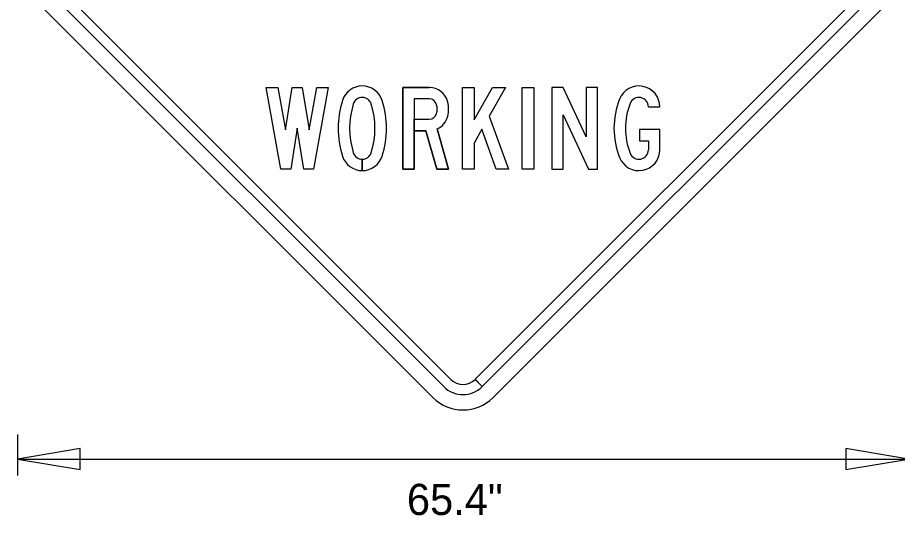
# Model space of a CAD drawing. Extents: x 0 to 770, y 0 to 495.
# Drawn here: x 425.3 to 524.2, y 356.5 to 412.5 of the extents above; entities that cross this region are included whole.
import ezdxf

# ---------------------------------------------------------------- set-up
doc = ezdxf.new("R2010")
doc.units = 0
for name, color, linetype in [('Dimension', 7, 'Continuous'), ('GSBWFill', 7, 'Continuous'), ('GSColorFill', 7, 'Continuous'), ('GSDims', 7, 'Continuous'), ('GSOutline', 7, 'Continuous'), ('TextStructures', 7, 'Continuous')]:
    doc.layers.add(name, color=color, linetype=linetype)

msp = doc.modelspace()

# ---------------------------------------------------------------- linework, layer by layer
at = {"layer": 'Dimension'}
for points in [[(425.301, 362.828), (432.318, 361.639), (432.318, 364.017)], [(525.425, 362.828), (518.409, 364.017), (518.409, 361.639)]]:
    msp.add_lwpolyline(points, close=True, dxfattribs=at)
at = {"layer": 'GSBWFill'}
for p, q in [((474.008, 371.785), (428.738, 417.055)), ((521.989, 417.055), (476.727, 371.793)), ((427.924, 416.242), (473.195, 370.972)), ((477.54, 370.98), (522.802, 416.242)), ((426.705, 415.022), (471.975, 369.752)), ((478.752, 369.752), (524.022, 415.022)), ((496.203, 402.424), (497.491, 402.424)), ((471.557, 401.021), (471.557, 401.021)), ((496.203, 398.583), (496.203, 397.594)), ((464.046, 395.248), (464.046, 396.536)), ((464.047, 396.536), (464.047, 395.248)), ((477.532, 370.972), (476.719, 371.785)), ((476.727, 371.793), (477.54, 370.98))]:
    msp.add_line(p, q, dxfattribs=at)
for points in [[(455.401, 399.848), (456.163, 404.609), (457.3, 404.609), (458.062, 399.848), (458.919, 404.609), (460.228, 404.609), (458.572, 395.409), (457.468, 395.409), (456.732, 400.009), (455.996, 395.409), (454.892, 395.409), (453.235, 404.609), (454.544, 404.609)], [(477.487, 399.91), (476.605, 398.353), (476.605, 395.409), (475.317, 395.409), (475.317, 404.609), (476.605, 404.609), (476.605, 400.967), (478.667, 404.609), (480.148, 404.609), (478.324, 401.389), (480.47, 395.409), (479.101, 395.409)], [(482.034, 404.609), (483.322, 404.609), (483.322, 395.409), (482.034, 395.409)], [(489.486, 395.409), (490.498, 395.409), (490.498, 404.609), (489.21, 404.609), (489.21, 399.05), (486.618, 404.609), (485.346, 404.609), (485.346, 395.409), (486.634, 395.409), (486.634, 401.527)]]:
    msp.add_lwpolyline(points, close=True, dxfattribs=at)
for points in [[(471.557, 403.321), (469.889, 403.321), (469.889, 395.409), (468.601, 395.409), (468.601, 404.609), (471.557, 404.609)], [(472.465, 399.933), (473.753, 395.409), (472.414, 395.409), (471.183, 399.733), (469.889, 399.733), (469.889, 401.021), (471.557, 401.021)], [(497.491, 397.594), (497.491, 399.871), (495.191, 399.871), (495.191, 398.583), (496.203, 398.583)]]:
    msp.add_lwpolyline(points, dxfattribs=at)
for centre, radius, start, end in [((464.046, 402.424), 2.346, 17.32827, 162.67173), ((471.557, 402.447), 2.162, 13.88654, 90), ((495.145, 402.424), 2.346, 0, 158.43141), ((471.787, 400.009), 10.455, 162.67173, 197.32827), ((471.787, 400.009), 9.167, 162.67173, 197.32827), ((464.046, 402.424), 1.058, 17.32827, 162.67173), ((456.305, 400.009), 9.167, 342.67173, 17.32827), ((456.305, 400.009), 10.455, 342.67173, 17.32827), ((471.557, 402.447), 0.874, 13.88654, 90), ((470.441, 402.171), 2.024, 346.11346, 13.88654), ((470.441, 402.171), 3.312, 346.11346, 13.88654), ((501.255, 400.009), 8.916, 158.43141, 201.5686), ((501.255, 400.009), 7.628, 158.4314, 201.56859), ((495.145, 402.424), 1.058, 0, 158.43141), ((471.557, 401.895), 0.874, 270, 346.11346), ((471.557, 401.895), 2.162, 294.82206, 346.11346), ((495.145, 397.594), 2.346, 201.56859, 0), ((495.145, 397.594), 1.058, 201.56859, 0), ((464.046, 397.594), 2.346, 197.32827, 270), ((464.046, 397.594), 1.058, 197.32827, 270), ((464.046, 397.594), 1.058, 270.02491, 342.67173), ((464.046, 397.594), 2.346, 270.01123, 342.67173), ((475.363, 373.14), 3.067, 225, 315), ((475.363, 373.14), 1.917, 225, 315), ((475.363, 373.14), 4.792, 225, 315)]:
    msp.add_arc(centre, radius, start, end, dxfattribs=at)
at = {"layer": 'GSColorFill'}
for p, q in [((496.203, 402.424), (497.491, 402.424)), ((471.557, 401.021), (471.557, 401.021)), ((496.203, 398.583), (496.203, 397.594)), ((464.046, 395.248), (464.046, 396.536)), ((464.047, 396.536), (464.047, 395.248))]:
    msp.add_line(p, q, dxfattribs=at)
for points in [[(455.401, 399.848), (456.163, 404.609), (457.3, 404.609), (458.062, 399.848), (458.919, 404.609), (460.228, 404.609), (458.572, 395.409), (457.468, 395.409), (456.732, 400.009), (455.996, 395.409), (454.892, 395.409), (453.235, 404.609), (454.544, 404.609)], [(477.487, 399.91), (476.605, 398.353), (476.605, 395.409), (475.317, 395.409), (475.317, 404.609), (476.605, 404.609), (476.605, 400.967), (478.667, 404.609), (480.148, 404.609), (478.324, 401.389), (480.47, 395.409), (479.101, 395.409)], [(482.034, 404.609), (483.322, 404.609), (483.322, 395.409), (482.034, 395.409)], [(489.486, 395.409), (490.498, 395.409), (490.498, 404.609), (489.21, 404.609), (489.21, 399.05), (486.618, 404.609), (485.346, 404.609), (485.346, 395.409), (486.634, 395.409), (486.634, 401.527)]]:
    msp.add_lwpolyline(points, close=True, dxfattribs=at)
for points in [[(471.557, 403.321), (469.889, 403.321), (469.889, 395.409), (468.601, 395.409), (468.601, 404.609), (471.557, 404.609)], [(472.465, 399.933), (473.753, 395.409), (472.414, 395.409), (471.183, 399.733), (469.889, 399.733), (469.889, 401.021), (471.557, 401.021)], [(497.491, 397.594), (497.491, 399.871), (495.191, 399.871), (495.191, 398.583), (496.203, 398.583)]]:
    msp.add_lwpolyline(points, dxfattribs=at)
for centre, radius, start, end in [((464.046, 402.424), 2.346, 17.32827, 162.67173), ((471.557, 402.447), 2.162, 13.88654, 90), ((495.145, 402.424), 2.346, 0, 158.43141), ((471.787, 400.009), 10.455, 162.67173, 197.32827), ((471.787, 400.009), 9.167, 162.67173, 197.32827), ((464.046, 402.424), 1.058, 17.32827, 162.67173), ((456.305, 400.009), 9.167, 342.67173, 17.32827), ((456.305, 400.009), 10.455, 342.67173, 17.32827), ((471.557, 402.447), 0.874, 13.88654, 90), ((470.441, 402.171), 2.024, 346.11346, 13.88654), ((470.441, 402.171), 3.312, 346.11346, 13.88654), ((501.255, 400.009), 8.916, 158.43141, 201.5686), ((501.255, 400.009), 7.628, 158.4314, 201.56859), ((495.145, 402.424), 1.058, 0, 158.43141), ((471.557, 401.895), 0.874, 270, 346.11346), ((471.557, 401.895), 2.162, 294.82206, 346.11346), ((495.145, 397.594), 2.346, 201.56859, 0), ((495.145, 397.594), 1.058, 201.56859, 0), ((464.046, 397.594), 2.346, 197.32827, 270), ((464.046, 397.594), 1.058, 197.32827, 270), ((464.046, 397.594), 1.058, 270.02491, 342.67173), ((464.046, 397.594), 2.346, 270.01123, 342.67173)]:
    msp.add_arc(centre, radius, start, end, dxfattribs=at)
at = {"layer": 'GSDims'}
for p, q in [((425.301, 365.588), (425.301, 360.988)), ((425.301, 362.828), (525.425, 362.828))]:
    msp.add_line(p, q, dxfattribs=at)
at = {"layer": 'GSOutline'}
for p, q in [((471.557, 404.609), (468.601, 404.609)), ((471.557, 403.321), (471.557, 403.321)), ((496.203, 402.424), (497.491, 402.424)), ((496.203, 398.583), (496.203, 397.594))]:
    msp.add_line(p, q, dxfattribs=at)
for points in [[(455.401, 399.848), (456.163, 404.609), (457.3, 404.609), (458.062, 399.848), (458.919, 404.609), (460.228, 404.609), (458.572, 395.409), (457.468, 395.409), (456.732, 400.009), (455.996, 395.409), (454.892, 395.409), (453.235, 404.609), (454.544, 404.609)], [(477.487, 399.91), (476.605, 398.353), (476.605, 395.409), (475.317, 395.409), (475.317, 404.609), (476.605, 404.609), (476.605, 400.967), (478.667, 404.609), (480.148, 404.609), (478.324, 401.389), (480.47, 395.409), (479.101, 395.409)], [(482.034, 404.609), (483.322, 404.609), (483.322, 395.409), (482.034, 395.409)], [(489.486, 395.409), (490.498, 395.409), (490.498, 404.609), (489.21, 404.609), (489.21, 399.05), (486.618, 404.609), (485.346, 404.609), (485.346, 395.409), (486.634, 395.409), (486.634, 401.527)]]:
    msp.add_lwpolyline(points, close=True, dxfattribs=at)
for points in [[(468.601, 404.609), (468.601, 395.409), (469.889, 395.409), (469.889, 399.733), (471.183, 399.733), (472.414, 395.409), (473.753, 395.409), (472.465, 399.933)], [(471.557, 403.321), (469.889, 403.321), (469.889, 401.021), (471.557, 401.021)], [(497.491, 397.594), (497.491, 399.871), (495.191, 399.871), (495.191, 398.583), (496.203, 398.583)]]:
    msp.add_lwpolyline(points, dxfattribs=at)
for centre, radius, start, end in [((464.046, 402.424), 2.346, 17.32827, 162.67173), ((471.557, 402.447), 2.162, 13.88654, 90), ((495.145, 402.424), 2.346, 0, 158.43141), ((471.787, 400.009), 10.455, 162.67173, 197.32827), ((471.787, 400.009), 9.167, 162.67173, 197.32827), ((464.046, 402.424), 1.058, 17.32827, 162.67173), ((456.305, 400.009), 9.167, 342.67173, 17.32827), ((456.305, 400.009), 10.455, 342.67173, 17.32827), ((471.557, 402.447), 0.874, 13.88654, 90), ((470.441, 402.171), 2.024, 346.11346, 13.88654), ((470.441, 402.171), 3.312, 346.11346, 13.88654), ((501.255, 400.009), 8.916, 158.43141, 201.5686), ((501.255, 400.009), 7.628, 158.4314, 201.56859), ((495.145, 402.424), 1.058, 0, 158.43141), ((471.557, 401.895), 0.874, 270, 346.11346), ((471.557, 401.895), 2.162, 294.82207, 346.11346), ((495.145, 397.594), 2.346, 201.56859, 0), ((495.145, 397.594), 1.058, 201.56859, 0), ((464.046, 397.594), 2.346, 197.32827, 342.67173), ((464.046, 397.594), 1.058, 197.32827, 342.67173)]:
    msp.add_arc(centre, radius, start, end, dxfattribs=at)

# ---------------------------------------------------------------- texts
at = {"layer": 'TextStructures'}
msp.add_text('65.4"', height=3.5, dxfattribs=at).set_placement((469.059, 356.537))

doc.saveas('drawing.dxf')
